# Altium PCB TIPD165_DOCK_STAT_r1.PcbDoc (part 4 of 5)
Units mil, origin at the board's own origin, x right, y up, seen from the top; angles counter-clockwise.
Board outline 6950 x 2800 mil, 2 copper layers (Primary Side, Secondary Side), stack 12.7 mil thick; 32 components, 163 nets, 1211 pads, 80 vias.
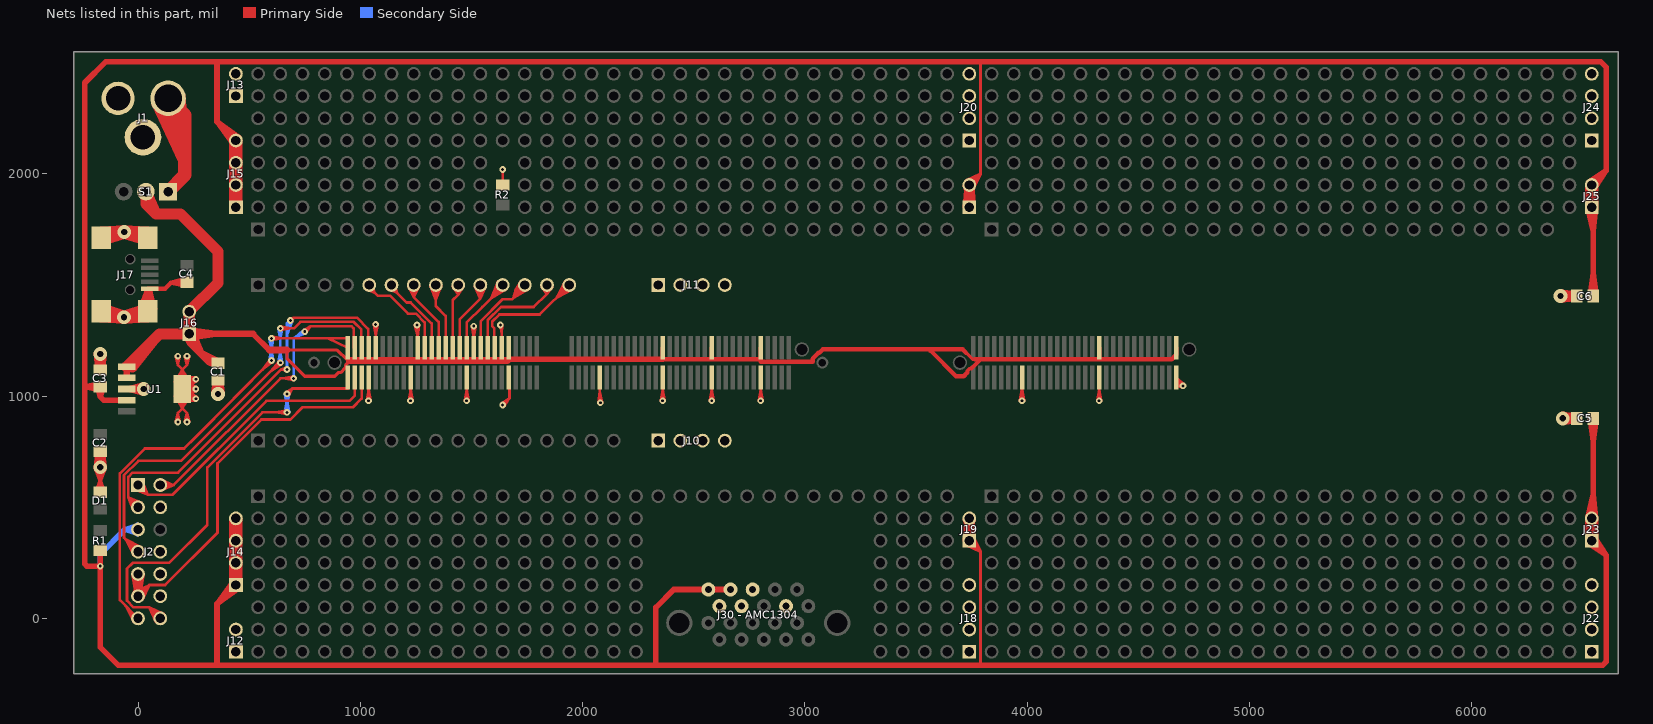
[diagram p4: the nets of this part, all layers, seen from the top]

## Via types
v1: diameter 30/30 (per signal layer), hole 13, Primary Side to Secondary Side, 70 vias
v2: diameter 62/62 (per signal layer), hole 28, Primary Side to Secondary Side, 9 vias
v3: diameter 30, hole 13, Primary Side to Secondary Side, 1 vias

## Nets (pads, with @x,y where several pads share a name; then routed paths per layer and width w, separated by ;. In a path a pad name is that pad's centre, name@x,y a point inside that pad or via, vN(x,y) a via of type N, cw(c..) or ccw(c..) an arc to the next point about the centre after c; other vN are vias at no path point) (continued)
$$$26262: pad.6@1040,1500 pad.24@1289.46,1217.86 | length 611.6
  Primary Side w12: pad.6@1024.56,1480.34 1065,1464.46 ; pad.6@1030.61,1491.01 1065,1464.46 ; pad.6@1051.63,1505.81 1065,1464.46 ; pad.24@1289.46,1217.86 1289.46,1331.14 1249.6,1371 1214.77,1371 1134.77,1451 1078.46,1451 1065,1464.46 ; 1065,1464.46 pad.6@1040,1500 1038.89,1499.17 1065,1464.46
$$$26267: pad.7@1140,1500 pad.26@1320.95,1217.86 | length 540.4
  Primary Side w12: pad.7@1124.56,1480.34 1165,1464.46 ; pad.7@1130.61,1491.01 1165,1464.46 ; pad.7@1151.63,1505.81 1165,1464.46 ; pad.26@1320.95,1217.86 1320.95,1326.52 1226.47,1421 1208.46,1421 1165,1464.46 ; 1165,1464.46 1138.89,1499.17 pad.7@1140,1500 1165,1464.46
$$$26270: pad.8@1240,1500 pad.28@1352.45,1217.86 | length 600.4
  Primary Side w12: pad.8@1215.67,1494.25 1240,1445.67 ; pad.8@1227.09,1498.44 1240,1445.67 ; pad.8@1252.91,1498.44 1240,1445.67 ; pad.8@1264.33,1494.25 1240,1445.67 ; pad.28@1352.45,1217.86 1352.45,1333.22 1240,1445.67 ; 1240,1445.67 pad.8@1240,1500 1240,1445.67
$$$26274: pad.9@1340,1500 pad.30@1383.94,1217.86 | length 635.3
  Primary Side w12: pad.9@1315.44,1495.34 1340,1433 ; pad.9@1327.06,1498.74 1340,1433 ; pad.9@1352.94,1498.74 1340,1433 ; pad.9@1364.56,1495.34 1340,1433 ; pad.30@1383.94,1217.86 1383.94,1360.4 1340,1404.34 pad.9@1340,1500 1340,1433
$$$26277: pad.10@1440,1500 pad.32@1415.44,1217.86 | length 512.3
  Primary Side w12: pad.32@1415.44,1217.86 1415.44,1431.44 1440,1456 ; pad.10@1416.03,1492.9 1440,1456 ; pad.10@1427.14,1498.08 1440,1456 ; pad.10@1452.86,1498.08 1440,1456 ; pad.10@1463.97,1492.9 1440,1456 ; 1440,1456 pad.10@1440,1500 1440,1456
$$$26281: pad.11@1540,1500 pad.34@1446.94,1217.86 | length 629.5
  Primary Side w12: pad.34@1446.94,1217.86 1446.94,1345.17 1540,1438.23 ; pad.11@1515.52,1494.94 1540,1438.23 ; pad.11@1527.07,1498.63 1540,1438.23 ; pad.11@1552.93,1498.63 1540,1438.23 ; pad.11@1564.48,1494.94 1540,1438.23 ; 1540,1438.23 pad.11@1540,1500 1540,1438.23
$$$26286: pad.12@1640,1500 pad.36@1478.43,1217.86 | length 744.8
  Primary Side w12: pad.36@1478.43,1217.86 1478.43,1331.03 1549.4,1402 1549.6,1402 1643.8,1496.2 pad.12@1640,1500 1588.43,1440.83 ; pad.12@1618.78,1513.21 1588.43,1440.83 ; pad.12@1629.53,1507.7 1588.43,1440.83 ; pad.12@1649.06,1490.68 1588.43,1440.83 ; pad.12@1655.99,1480.78 1588.43,1440.83
$$$26290: pad.13@1740,1500 pad.40@1541.43,1217.86 | length 863.2
  Primary Side w12: pad.40@1541.43,1217.86 1541.43,1336.76 1640.66,1436 1683.6,1436 1743.8,1496.2 pad.13@1740,1500 1689.12,1441.52 ; 1697.23,1476.63 1718.74,1513.15 1689.12,1441.52 ; 1698.92,1480.81 1689.12,1441.52 ; pad.13@1729.51,1507.68 1689.12,1441.52 ; pad.13@1749.06,1490.67 1689.12,1441.52 ; pad.13@1755.97,1480.76 1689.12,1441.52
$$$26294: pad.14@1840,1500 pad.42@1572.92,1217.86 | length 679.2
  Primary Side w12: pad.42@1572.92,1217.86 1572.92,1341.39 1632.53,1401 1780,1401 1839,1460 ; pad.14@1816.06,1492.79 1839,1460 ; pad.14@1827.12,1498.21 1839,1460 ; pad.14@1852.77,1497.57 1839,1460 ; pad.14@1863.55,1491.6 1839,1460 ; 1839,1460 1839,1499 pad.14@1840,1500 1839,1460
$$$26299: pad.15@1940,1500 pad.44@1604.42,1217.86 | length 936.2
  Primary Side w12: pad.44@1604.42,1217.86 1603,1219.28 1603,1305 1593,1315 1593,1334.6 1625.4,1367 1807,1367 pad.15@1940,1500 1883.54,1443.54 ; pad.15@1919.77,1514.69 1883.54,1443.54 ; pad.15@1930.09,1508.41 1883.54,1443.54 ; pad.15@1948.41,1490.09 1883.54,1443.54 ; pad.15@1954.69,1479.77 1883.54,1443.54
$$$26449: J1.2 S1.1 | length 1347.6
  Primary Side w60: J1.2@88.03,2322.87 210,2061.42 ; S1.1@135,1920 210,1995 210,2265 J1.2@135,2340 210,2061.42 ; J1.2@184.23,2348.77 210,2061.42
+3V3: "J30 - AMC1304.a8" "J30 - AMC1304.a10" C3.2 C5.2 C6.2 J2.5 J14.1 J14.2 J14.3 J14.4 J15.1 J15.2 J15.3 J15.4 J19.1 J19.2 J23.1 J23.2 J25.1 J25.2 pad.1@3740,1850 pad.2@3740,1950 R1.1 U1.4 | length 36424.3
  Primary Side w15: J19.1@3716.55,348.44 J19.2@3723.13,426.6 ; J19.1@3716.57,351.82 J19.2@3734.14,426.15 ; pad.1@3716.55,1848.44 pad.2@3723.13,1926.6 ; pad.1@3716.57,1851.82 pad.2@3734.14,1926.15 ; J19.1@3716.78,353.63 J19.2@3740,426 ; J19.2@3716.78,446.37 J19.1@3740,374 ; pad.1@3716.78,1853.63 pad.2@3740,1926 ; pad.2@3716.78,1946.37 pad.1@3740,1874 ; J19.1@3717.13,355.39 J19.2@3745.86,426.15 ; pad.1@3717.13,1855.39 pad.2@3745.86,1926.15 ; J19.1@3718.07,358.44 J19.2@3756.87,426.6 ; pad.1@3718.07,1858.44 pad.2@3756.87,1926.6 ; J19.1@3726.38,330.85 3790,300 ; pad.2@3726.38,1969.15 3790,2000 ; J19.1@3731.5,349.82 J19.2@3734.14,426.15 ; J19.1@3731.51,350.48 J19.2@3740,426 ; J19.2@3731.51,449.52 J19.1@3740,374 ; pad.1@3731.5,1849.82 pad.2@3734.14,1926.15 ; pad.1@3731.51,1850.48 pad.2@3740,1926 ; pad.2@3731.51,1949.52 pad.1@3740,1874 ; J19.1@3731.57,351.12 J19.2@3745.86,426.15 ; pad.1@3731.57,1851.12 pad.2@3745.86,1926.15 ; J19.1@3731.61,348.62 J19.2@3723.13,426.6 ; pad.1@3731.61,1848.62 pad.2@3723.13,1926.6 ; J19.1@3731.81,352.28 J19.2@3756.87,426.6 ; pad.1@3731.81,1852.28 pad.2@3756.87,1926.6 ; J19.1@3734.36,343.64 3790,300 ; pad.2@3734.36,1956.36 3790,2000 ; J19.2@3740,450 J19.1@3740,350 ; J19.1@3746.36,355.64 3790,300 ; pad.2@3746.36,1944.36 3790,2000 ; J19.1@3748.19,352.28 J19.2@3723.13,426.6 ; pad.1@3748.19,1852.28 pad.2@3723.13,1926.6 ; J19.1@3748.39,348.62 J19.2@3756.87,426.6 ; pad.1@3748.39,1848.62 pad.2@3756.87,1926.6 ; J19.1@3748.43,351.12 J19.2@3734.14,426.15 ; pad.1@3748.43,1851.12 pad.2@3734.14,1926.15 ; J19.1@3748.5,349.82 J19.2@3745.86,426.15 ; J19.1@3748.49,350.48 J19.2@3740,426 ; J19.2@3748.49,449.52 J19.1@3740,374 ; pad.1@3748.5,1849.82 pad.2@3745.86,1926.15 ; pad.1@3748.49,1850.48 pad.2@3740,1926 ; pad.2@3748.49,1949.52 pad.1@3740,1874 ; J19.1@3759.15,363.62 3790,300 ; pad.2@3759.15,1936.38 3790,2000 ; J19.1@3761.93,358.44 J19.2@3723.13,426.6 ; pad.1@3761.93,1858.44 pad.2@3723.13,1926.6 ; J19.1@3762.87,355.39 J19.2@3734.14,426.15 ; pad.1@3762.87,1855.39 pad.2@3734.14,1926.15 ; J19.1@3763.22,353.63 J19.2@3740,426 ; J19.2@3763.22,446.37 J19.1@3740,374 ; pad.1@3763.22,1853.63 pad.2@3740,1926 ; pad.2@3763.22,1946.37 pad.1@3740,1874 ; J19.1@3763.45,348.44 J19.2@3756.87,426.6 ; J19.1@3763.43,351.82 J19.2@3745.86,426.15 ; pad.1@3763.45,1848.44 pad.2@3756.87,1926.6 ; pad.1@3763.43,1851.82 pad.2@3745.86,1926.15 ; 3790,-210 3790,300 ; 3790,2505 3790,2000 ; J19.2@3723.13,426.6 J19.1@3740,350 ; pad.2@3723.13,1926.6 pad.1@3740,1850 ; J19.2@3734.14,426.15 J19.1@3740,350 ; pad.2@3734.14,1926.15 pad.1@3740,1850 ; J19.1@3740,350 3790,300 ; J19.1@3740,350 J19.2@3745.86,426.15 ; J19.1@3740,350 J19.2@3756.87,426.6 ; pad.1@3740,1850 pad.2@3740,1950 3790,2000 ; pad.1@3740,1850 pad.2@3745.86,1926.15 ; pad.1@3740,1850 pad.2@3756.87,1926.6
  Primary Side w25: C3.2@-182.87,1040.64 -170,997 ; C3.2@-175.28,1029.56 -240,1042.5 ; C3.2@-175.28,1055.44 -240,1042.5 ; C3.2@-174,1042.5 -240,1042.5 ; R1.1@-170,305 v1(-170,235) ; C3.2@-157.13,1040.64 -170,997 ; U1.4@-76,982 -155,982 ; U1.4@-51,982 -155,982 ; J14.1@421.58,148.29 J14.2@421.58,248.29 ; J14.1@421.58,151.71 J14.2@440,250 ; J14.2@421.58,251.71 J14.3@440,350 ; J14.3@421.58,351.71 J14.4@440,450 ; J15.1@421.58,1848.29 J15.2@421.58,1948.29 ; J15.1@421.58,1851.71 J15.2@440,1950 ; J15.2@421.58,1951.71 J15.3@440,2050 ; J15.3@421.58,2051.71 J15.4@440,2150 ; J14.1@422.21,155.08 J14.2@458.42,248.29 ; J14.2@422.21,255.08 J14.3@458.42,348.29 ; J14.3@422.21,355.08 J14.4@458.42,448.29 ; J15.1@422.21,1855.08 J15.2@458.42,1948.29 ; J15.2@422.21,1955.08 J15.3@458.42,2048.29 ; J15.3@422.21,2055.08 J15.4@458.42,2148.29 ; J14.1@425.94,162.02 355.97,65.97 ; J15.4@425.94,2137.98 355.97,2234.03 J15.4@452.02,2164.06 ; J14.1@452.02,135.94 355.97,65.97 ; J14.1@457.79,155.08 J14.2@421.58,248.29 ; J14.2@457.79,255.08 J14.3@421.58,348.29 ; J14.3@457.79,355.08 J14.4@421.58,448.29 ; J15.1@457.79,1855.08 J15.2@421.58,1948.29 ; J15.2@457.79,1955.08 J15.3@421.58,2048.29 ; J15.3@457.79,2055.08 J15.4@421.58,2148.29 ; J14.1@458.42,148.29 J14.2@458.42,248.29 ; J14.1@458.42,151.71 J14.2@440,250 ; J14.2@458.42,251.71 J14.3@440,350 ; J14.3@458.42,351.71 J14.4@440,450 ; J15.1@458.42,1848.29 J15.2@458.42,1948.29 ; J15.1@458.42,1851.71 J15.2@440,1950 ; J15.2@458.42,1951.71 J15.3@440,2050 ; J15.3@458.42,2051.71 J15.4@440,2150 ; 2665.31,130 2565.31,130 2410,130 2330,50 2330,-210 ; J23.1@6521.58,348.29 J23.2@6521.58,448.29 ; J23.1@6521.58,351.71 J23.2@6540,450 ; J25.1@6521.58,1848.29 J25.2@6521.58,1948.29 ; J25.1@6521.58,1851.71 J25.2@6540,1950 ; J23.2@6521.73,452.88 6547.5,557.02 ; J25.1@6521.73,1847.12 6547.5,1743 ; J23.1@6522.21,355.08 J23.2@6558.42,448.29 ; J25.1@6522.21,1855.08 J25.2@6558.42,1948.29 ; J23.1@6528.3,335.67 6605,285 ; J25.2@6528.3,1964.33 6605,2015 ; C5.2@6534.53,895.16 6547.5,795.5 ; C6.2@6534.53,1454.84 6547.5,1554.5 ; C5.2@6547.5,896 6547.5,795.5 ; C5.2@6547.5,900 6547.5,457.5 J23.2@6540,450 ; C6.2@6547.5,1450 6547.5,1842.5 J25.1@6540,1850 ; C6.2@6547.5,1454 6547.5,1554.5 ; J23.1@6554.33,361.7 6605,285 ; J25.2@6554.33,1938.3 6605,2015 ; J23.1@6557.79,355.08 J23.2@6521.58,448.29 ; J25.1@6557.79,1855.08 J25.2@6521.58,1948.29 ; J23.1@6558.42,348.29 J23.2@6558.42,448.29 ; J23.1@6558.42,351.71 J23.2@6540,450 ; J25.1@6558.42,1848.29 J25.2@6558.42,1948.29 ; J25.1@6558.42,1851.71 J25.2@6540,1950 ; J23.2@6558.5,450.3 6547.5,557.02 ; J25.1@6558.5,1849.7 6547.5,1743 ; C5.2@6560.47,895.16 6547.5,795.5 ; C6.2@6560.47,1454.84 6547.5,1554.5 ; -240,1042.5 C3.2@-170,1042.5 -170,997 ; -240,1042.5 -240,245 -230,235 v1(-170,235) ; -240,1042.5 -240,2410 -145,2505 355,2505 ; v1(-170,235) -170,-130 -90,-210 355,-210 ; -170,997 -155,982 ; 355,-210 355,65 J14.1@440,150 ; 355,-210 2330,-210 ; 355,2505 355,2235 J15.4@440,2150 ; 355,2505 3790,2505 6580,2505 6605,2480 6605,2015 ; 355.97,65.97 J14.1@440,150 ; J14.2@421.58,248.29 J14.1@440,150 ; J14.2@421.58,248.29 J14.3@421.58,348.29 ; J14.3@421.58,348.29 J14.2@440,250 ; J14.3@421.58,348.29 J14.4@421.58,448.29 ; J14.4@421.58,448.29 J14.3@440,350 ; J15.2@421.58,1948.29 J15.1@440,1850 ; J15.2@421.58,1948.29 J15.3@421.58,2048.29 ; J15.3@421.58,2048.29 J15.2@440,1950 ; J15.3@421.58,2048.29 J15.4@421.58,2148.29 ; J15.4@421.58,2148.29 J15.3@440,2050 ; J14.1@440,150 J14.2@440,250 ; J14.1@440,150 J14.2@458.42,248.29 ; J14.2@440,250 J14.3@440,350 ; J14.2@440,250 J14.3@458.42,348.29 ; J14.3@440,350 J14.4@440,450 ; J14.3@440,350 J14.4@458.42,448.29 ; J15.1@440,1850 J15.2@440,1950 ; J15.1@440,1850 J15.2@458.42,1948.29 ; J15.2@440,1950 J15.3@440,2050 ; J15.2@440,1950 J15.3@458.42,2048.29 ; J15.3@440,2050 J15.4@440,2150 ; J15.3@440,2050 J15.4@458.42,2148.29 ; J14.2@458.42,248.29 J14.3@458.42,348.29 ; J14.3@458.42,348.29 J14.4@458.42,448.29 ; J15.2@458.42,1948.29 J15.3@458.42,2048.29 ; J15.3@458.42,2048.29 J15.4@458.42,2148.29 ; 2330,-210 3790,-210 6590,-210 6605,-195 6605,285 ; J23.2@6521.58,448.29 J23.1@6540,350 ; J25.2@6521.58,1948.29 J25.1@6540,1850 ; J23.1@6540,350 6605,285 ; J23.1@6540,350 J23.2@6540,450 ; J23.1@6540,350 J23.2@6558.42,448.29 ; J23.2@6540,450 6547.5,557.02 ; J25.1@6540,1850 J25.2@6540,1950 ; J25.1@6540,1850 J25.2@6558.42,1948.29 ; J25.1@6540,1850 6547.5,1743 ; J25.2@6540,1950 6605,2015
  Secondary Side w25: v1(-170,235) -170,290 -60,400 ; J2.5@-2.85,381.72 -60,400 ; J2.5@-2.85,418.28 -60,400 ; J2.5@0,400 -60,400
+5V: C1.2 J16.1 J16.2 pad.48@1667.41,1217.86 pad.84@2360.32,1217.86 pad.98@2580.8,1217.86 pad.112@2801.27,1217.86 pad.158@4323.63,1217.86 pad.180@4670.09,1217.86 S1.2 U1.1 U1.2 | length 8765.2
  Primary Side w12: C1.2@357.5,1150 C1.2@360,1147.5 ; pad.48@1667.41,1165 pad.48@1667.41,1217.86
  Primary Side w15: 944.58,1154.61 946.45,1156.48 ; 949.97,1160 946.45,1156.48 ; 3725,1195 3755,1165 3765,1165 ; 946.45,1156.48 940,1162.92 895,1207.5 670,1207.5 670,1170 750,1090 885,1090 900.99,1105.99 910.99,1105.99 932.97,1127.97 932.97,1137.97 948.96,1153.96 946.45,1156.48
  Primary Side w17: 3729.86,1104.86 3731.36,1106.36 3731.36,1114.04 3740.44,1123.12 3748.12,1123.12 3749.62,1124.62
  Primary Side w20: pad.84@2360.32,1217.86 2360,1165 2579,1165 pad.98@2580,1166 ; pad.98@2580.8,1217.86 2580,1217.86 pad.98@2580,1166 ; pad.112@2801.27,1217.86 2801,1217.86 pad.112@2801,1166 ; 3725,1195 3710,1210 3565,1210 ; 3729.86,1104.86 3715,1090 3680,1090 3565,1205 3565,1210 ; 3749.62,1124.62 3790,1165 ; 3765,1165 3790,1165 ; pad.158@4323.63,1217.86 4324,1217.86 4324,1166 4650,1166 4670,1186 4670,1217.77 pad.180@4670.09,1217.86 ; 4347,1165 3790,1165 ; pad.98@2580,1166 pad.112@2801,1166 ; pad.112@2801,1166 2801,1155 3035.29,1155 3035.29,1168.96 3060.8,1194.47 3064.47,1194.47 3080,1210 3565,1210
  Primary Side w25: J16.1@215.01,1269.16 293.37,1176.63 ; J16.1@246.46,1288.44 293.37,1176.63 ; C1.2@348.28,1137.04 259.11,1210.89 ; C1.2@357.5,1150 320,1150 ; C1.2@362.5,1158.76 259.11,1210.89 ; 517.5,1280 590,1207.5 ; pad.48@1667.41,1165 pad.84@2360,1165 ; 230,1240 J16.1@230,1280 ; 230,1240 320,1150 ; 230,1240 248,1275.72 230,1240 ; 230,1240 212,1275.72 230,1240 ; 230,1240 J16.1@230,1280 ; J16.1@230,1280 293.37,1176.63 ; 259.11,1210.89 C1.2@356,1147.5 ; 320,1150 352.78,1134.91 320,1150 ; 320,1150 354.55,1160.42 320,1150 ; 320,1150 C1.2@356,1147.5 ; 320,1150 C1.2@356,1147.5
  Primary Side w30: U1.2@-51,1082 U1.1@-51,1132 ; J16.1@230,1280 517.5,1280 ; J16.1@231.06,1264.03 351,1280 J16.1@231.06,1295.97 ; 590,1207.5 670,1207.5 ; 949.97,1160 1662.41,1160 pad.48@1667.41,1165
  Primary Side w50: U1.1@-51,1132 97,1280 J16.1@230,1280 J16.2@230,1380 360,1510 360,1650 190,1820 80,1820 ; U1.1@-26,1132 70.07,1253.07 ; 35,1865 S1.2@35,1920 ; 35,1865 80,1820 ; 35,1865 S1.2@35,1920 ; S1.2@35,1920 80,1820
\TRST\: J2.2 pad.4@974.5,1217.86 | length 1992.5
  Primary Side w12: J2.2@100,600 160,600 ; J2.2@101.41,587.08 160,600 ; J2.2@101.41,612.92 160,600 ; J2.2@105.21,575.55 160,600 ; J2.2@105.21,624.45 160,600 ; v1@699.21,1071.04 649,1080 ; v1@699.21,1088.96 649,1080 ; v1@744.5,1297.12 775,1315 ; v1(750,1290) 775,1315 ; v1@757.12,1284.5 775,1315 ; pad.4@974.5,1217.86 970,1217.86 970,1305 960,1315 775,1315 ; 160,600 640,1080 v1(700,1080) 649,1080
  Secondary Side w12: v1(700,1080) 700,1260 740,1290 v1(750,1290) 702.96,1262.22 ; v1@744.8,1297.35 702.96,1262.22 ; v1@753.92,1281.9 702.96,1262.22
EMU0: J2.13 pad.2@943,1217.86 | length 2801.4
  Primary Side w12: J2.13@-20.23,-14.69 -56.46,56.46 J2.13@-9.91,-8.41 ; J2.13@0,0 -82,82 -82,652.12 30.44,764.56 207.56,764.56 258,815 v1(600,1160) 559.79,1119.43 ; v1@593.13,1165.81 559.79,1119.43 ; v1(600,1260) 943,1260 pad.2@943,1217.86 852.46,1260 ; v1@600.79,1251.04 651,1260 v1@600.79,1268.96 ; v1@605.87,1153.18 559.79,1119.43
  Secondary Side w12: v1@591.04,1160.79 600,1211 v1@608.96,1160.79 ; v1@591.04,1259.21 600,1209 v1@608.96,1259.21 ; v1(600,1160) v1(600,1260)
EMU1: J2.14 pad.1@943,1084 | length 2612.7
  Primary Side w12: J2.14@79.48,-14.27 50,50 ; J2.14@90,-8.31 50,50 ; J2.14@100,0 50,50 ; J2.14@108.31,10 50,50 ; J2.14@114.27,20.52 50,50 ; v1@664.54,1017.15 694,1034 ; v1@669.21,918.04 619,927 ; v1@669.21,935.96 619,927 ; v1(670,1010) 694,1034 ; v1@677.15,1004.54 694,1034 ; pad.1@943,1084 943,1034 694,1034 ; 50,50 -20,50 -50,80 -50,224 -24,250 140,250 311.37,421.37 311.37,678.63 559.75,927 v1(670,927) 619,927
  Secondary Side w12: v1@661.04,927.79 670,978 v1@678.96,927.79 ; v1@661.04,1009.21 670,959 v1@678.96,1009.21 ; v1(670,927) v1(670,1010)
GND: "J30 - AMC1304.a3" "J30 - AMC1304.a6" "J30 - AMC1304.a7" "J30 - AMC1304.a9" C1.1 C2.1 C3.1 C4.1 C5.1 C6.1 D1.1 J1.1 J1.3 J2.4 J2.8 J2.10 J2.12 J10.1 J10.2 J10.3 J10.4 J11.1 J11.2 J11.3 J11.4 J12.1 J12.2 J13.1 J13.2 J17.5 J17.6 J17.7 J17.8 J17.9 J18.1 J18.2 J18.3 J18.4 J20.1 J20.2 J20.3 J20.4 J22.1 J22.2 J22.3 J22.4 J24.1 J24.2 J24.3 J24.4 pad.7@1037.49,1084 pad.10@1068.98,1217.86 pad.19@1226.46,1084 pad.22@1257.96,1217.86 pad.35@1478.43,1084 pad.38@1509.93,1217.86 pad.46@1635.91,1217.86 pad.47@1667.41,1084 pad.65@2076.86,1084 pad.83@2360.32,1084 pad.97@2580.8,1084 pad.111@2801.27,1084 pad.135@3977.17,1084 pad.157@4323.63,1084 pad.179@4670.09,1084 R2.2 U1.3 U1.6 | length 26797.5
  Primary Side w12: v2@-194.91,677.9 C2.1@-188.09,745.87 ; v2@-194.91,682.12 C2.1@-176.85,746.84 ; v2@-194.91,1187.88 C3.1@-176.85,1123.16 ; v2@-194.91,1192.1 C3.1@-188.09,1124.13 ; v2@-194.56,675.34 -170,613 ; v2@-194.56,684.66 C2.1@-170,747 ; v2@-194.56,1185.34 C3.1@-170,1123 ; v2@-193.96,687.13 C2.1@-163.15,746.84 ; v2@-193.96,1182.87 C3.1@-163.15,1123.16 ; v2@-192.49,690.92 C2.1@-151.91,745.87 ; v2@-192.49,1179.08 C3.1@-151.91,1124.13 ; D1.1@-189.25,570.59 -170,629 ; C2.1@-189.25,749.41 v2@-170,691 ; C3.1@-189.25,1120.59 v2@-170,1179 ; v2@-183,679.93 C2.1@-176.85,746.84 ; v2@-183,1190.07 C3.1@-176.85,1123.16 ; v2@-182.94,678.74 -170,613 ; v2@-182.94,681.26 C2.1@-170,747 ; v2@-182.94,1188.74 C3.1@-170,1123 ; v2@-182.81,677.77 C2.1@-188.09,745.87 ; v2@-182.81,1192.23 C3.1@-188.09,1124.13 ; v2@-182.74,682.57 C2.1@-163.15,746.84 ; v2@-182.74,1187.43 C3.1@-163.15,1123.16 ; v2@-182.15,684.62 C2.1@-151.91,745.87 ; v2@-182.15,1185.38 C3.1@-151.91,1124.13 ; D1.1@-177.49,567.96 -170,629 ; C2.1@-177.49,752.04 v2@-170,691 ; C3.1@-177.49,1117.96 v2@-170,1179 ; D1.1@-170,567.5 v2(-170,680) ; C2.1@-170,752.5 v2(-170,680) ; C3.1@-170,1117.5 v2(-170,1190) ; D1.1@-162.51,567.96 -170,629 ; C2.1@-162.51,752.04 v2@-170,691 ; C3.1@-162.51,1117.96 v2@-170,1179 ; v2@-157.85,684.62 C2.1@-188.09,745.87 ; v2@-157.85,1185.38 C3.1@-188.09,1124.13 ; v2@-157.26,682.57 C2.1@-176.85,746.84 ; v2@-157.26,1187.43 C3.1@-176.85,1123.16 ; v2@-157.19,677.77 C2.1@-151.91,745.87 ; v2@-157.19,1192.23 C3.1@-151.91,1124.13 ; v2@-157.06,678.74 -170,613 ; v2@-157.06,681.26 C2.1@-170,747 ; v2@-157.06,1188.74 C3.1@-170,1123 ; v2@-157,679.93 C2.1@-163.15,746.84 ; v2@-157,1190.07 C3.1@-163.15,1123.16 ; D1.1@-150.75,570.59 -170,629 ; C2.1@-150.75,749.41 v2@-170,691 ; C3.1@-150.75,1120.59 v2@-170,1179 ; v2@-147.51,690.92 C2.1@-188.09,745.87 ; v2@-147.51,1179.08 C3.1@-188.09,1124.13 ; v2@-146.04,687.13 C2.1@-176.85,746.84 ; v2@-146.04,1182.87 C3.1@-176.85,1123.16 ; v2@-145.44,675.34 -170,613 ; v2@-145.44,684.66 C2.1@-170,747 ; v2@-145.44,1185.34 C3.1@-170,1123 ; v2@-145.09,677.9 C2.1@-151.91,745.87 ; v2@-145.09,682.12 C2.1@-163.15,746.84 ; v2@-145.09,1187.88 C3.1@-163.15,1123.16 ; v2@-145.09,1192.1 C3.1@-151.91,1124.13 ; U1.6@166.22,999.97 199,945 ; U1.6@166.22,1064.03 199,1119 ; v1@170.06,885.01 179,924 ; v1@170.06,1178.99 179,1140 ; U1.6@177.33,1005.22 199,945 ; U1.6@177.33,1058.78 199,1119 ; v1(179,884) 179,924 ; v1@187.94,885.01 179,924 ; v1@187.94,1178.99 179,1140 ; U1.6@189.03,1008.22 199,945 ; U1.6@189.03,1055.78 199,1119 ; U1.6@195.49,987.28 v1(260,988) ; U1.6@195.49,1076.72 v1(260,1076) ; U1.6@196.49,999.32 v1(260,988) ; U1.6@196.49,1064.68 v1(260,1076) ; U1.6@196.8,975.07 v1(260,988) ; U1.6@196.8,1088.93 v1(260,1076) ; U1.6@199.82,1022.03 v1(260,1032) ; U1.6@199.82,1041.97 v1(260,1032) ; U1.6@202.97,1010.36 v1(260,1032) ; U1.6@202.97,1053.64 v1(260,1032) ; U1.6@202.98,1018.17 v1(260,988) ; U1.6@202.98,1045.83 v1(260,1076) ; U1.6@208.48,999.35 v1(260,1032) ; U1.6@208.48,1064.65 v1(260,1032) ; U1.6@208.97,1008.22 199,945 ; U1.6@208.97,1055.78 199,1119 ; U1.6@209.6,1028.28 v1(260,988) ; U1.6@209.6,1035.72 v1(260,1076) ; v1@211.06,885.01 220,924 ; v1@211.06,1178.99 220,1140 ; U1.6@218.15,1026.9 v1(260,1076) ; U1.6@218.15,1037.1 v1(260,988) ; v1(220,884) 220,924 ; U1.6@220.67,1005.22 199,945 ; U1.6@220.67,1058.78 199,1119 ; v1@228.94,885.01 220,924 ; v1@228.94,1178.99 220,1140 ; U1.6@231.78,999.97 199,945 ; U1.6@231.78,1064.03 199,1119 ; v1@252.7,982.73 U1.6@223.86,1030.4 ; v1@252.7,1081.27 U1.6@223.86,1033.6 ; v1@253.83,981.45 U1.6@216.88,1022.46 ; v1@253.83,1082.55 U1.6@216.88,1041.54 ; v1@254.56,1024.83 U1.6@214.59,1060.78 ; v1@254.56,1039.17 U1.6@214.59,1003.22 ; v1@255.13,980.43 U1.6@213.18,1012.78 ; v1@255.13,1083.57 U1.6@213.18,1051.22 ; v1@256.09,1023.89 U1.6@211.34,1050.46 ; v1@256.09,1040.11 U1.6@211.34,1013.54 ; v1@256.34,979.78 U1.6@210.96,1004.88 ; v1@256.34,1084.22 U1.6@210.96,1059.12 ; v1@257.43,996.63 U1.6@209.73,977.72 ; v1@257.43,1067.37 U1.6@209.73,1086.28 ; v1@257.65,979.31 U1.6@209.56,996.99 ; v1@257.65,1084.69 U1.6@209.56,1067.01 ; v1@257.76,1023.28 U1.6@209.48,1040.37 ; v1@257.76,1040.72 U1.6@209.48,1023.63 ; v1@259.11,996.96 U1.6@209,987.43 ; v1@259.11,1067.04 U1.6@209,1076.57 ; v1@259.21,979.04 U1.6@209,988 ; v1@259.21,996.96 U1.6@209,988 ; v1@259.21,1023.04 U1.6@209,1032 ; v1@259.21,1040.96 U1.6@209,1032 ; v1@259.21,1067.04 U1.6@209,1076 ; v1@259.21,1084.96 U1.6@209,1076 ; v1@259.31,979.03 U1.6@209,987.43 ; v1@259.31,1084.97 U1.6@209,1076.57 ; v1@260.68,1023.03 U1.6@209.48,1023.63 ; v1@260.68,1040.97 U1.6@209.48,1040.37 ; v1@260.79,996.96 U1.6@209.56,996.99 ; v1@260.79,1067.04 U1.6@209.56,1067.01 ; v1@261.02,979.06 U1.6@209.73,977.72 ; v1@261.02,1084.94 U1.6@209.73,1086.28 ; v1@262.18,996.73 U1.6@210.96,1004.88 ; v1@262.18,1067.27 U1.6@210.96,1059.12 ; v1@262.45,1023.34 U1.6@211.34,1013.54 ; v1@262.45,1040.66 U1.6@211.34,1050.46 ; v1@263.52,996.28 U1.6@213.18,1012.78 ; v1@263.52,1067.72 U1.6@213.18,1051.22 ; v1@264.16,1024.02 U1.6@214.59,1003.22 ; v1@264.16,1039.98 U1.6@214.59,1060.78 ; v1@265.03,995.47 U1.6@216.88,1022.46 ; v1@265.03,1068.53 U1.6@216.88,1041.54 ; v1@266.36,994.37 U1.6@223.86,1030.4 ; v1@266.36,1069.63 U1.6@223.86,1033.6 ; v1@1028.04,979.79 1037,1030 v1@1045.96,979.79 ; v1(1037,979) 1037,1038 1037.49,1038 pad.7@1037.49,1084 ; v1@1060.04,1322.21 1069,1272 v1@1077.96,1322.21 ; pad.10@1068.98,1217.86 1068.98,1262 v1(1069,1323) ; v1@1217.04,979.79 1226,1030 v1@1234.96,979.79 ; v1(1226,979) 1226,1038 1226.46,1038 pad.19@1226.46,1084 ; v1@1246.1,1318.69 pad.22@1257.96,1268.79 ; pad.22@1257.96,1217.86 1257.96,1320 v1(1255,1320) pad.22@1257.96,1268.79 ; v1@1264,1319.73 pad.22@1257.96,1268.79 ; v1@1469.04,979.87 1478.43,1030 ; pad.35@1478.43,1084 1478.43,979 v1(1478,979) 1478.43,1030 ; v1@1486.97,979.72 1478.43,1030 ; v1@1501.03,1314.22 pad.38@1509.93,1264 ; pad.38@1509.93,1217.86 1509.93,1263 v1(1510,1315) pad.38@1509.93,1264 ; v1@1518.96,1314.19 pad.38@1509.93,1264 ; v1(1630,1320) 1635.91,1280 ; v1@1634.32,966.98 1670.93,990.93 ; pad.46@1635.91,1217.86 1635.91,1280 ; v1@1638.99,1320.32 1635.91,1280 ; v1(1640,960) 1670.93,990.93 ; R2.2@1640,1950 v3(1640,2020) ; v1@1646.98,954.32 1670.93,990.93 ; pad.47@1667.41,1084 1670.93,1084 1670.93,990.93 ; v1@2071,970.24 2076.86,1021.31 ; pad.65@2076.86,1084 2076.86,973.14 v1(2080,970) 2076.86,1021.31 ; v1@2088.9,971.33 2076.86,1021.31 ; v1@2351.04,979.85 2360.32,1030 ; pad.83@2360.32,1084 2360.32,979 v1(2360,979) 2360.32,1030 ; v1@2368.97,979.74 2360.32,1030 ; v1@2572.03,979.76 2580.81,1030 ; pad.97@2580.8,1084 2580.8,1035 v1(2581,979) 2580.81,1030 ; v1@2589.96,979.83 2580.81,1030 ; v1@2792.04,979.79 2801,1030 v1@2809.96,979.79 ; v1(2801,979) 2801,1035 2801.27,1035 pad.111@2801.27,1084 ; v1@3968.04,979.79 3977,1030 v1@3985.96,979.79 ; v1(3977,979) 3977,1039 3977.17,1039 pad.135@3977.17,1084 ; v1@4315.04,979.79 4324,1030 v1@4332.96,979.79 ; pad.157@4323.63,1084 4323.63,1039 4324,1039 v1(4324,979) ; v1@4693.53,1040.99 pad.179@4670.09,1084 ; v1@4699.69,1037.1 pad.179@4670.09,1046 ; v1@4699.69,1054.9 pad.179@4670.09,1046 ; v1@4707.43,1052.3 pad.179@4670.09,1084 ; v2@6397.77,1437.19 C6.1@6465.87,1431.91 ; v2@6397.77,1462.81 C6.1@6465.87,1468.09 ; v2@6397.9,1425.09 C6.1@6465.87,1431.91 ; v2@6397.9,1474.91 C6.1@6465.87,1468.09 ; v2@6399.93,1437 C6.1@6466.84,1443.15 ; v2@6399.93,1463 C6.1@6466.84,1456.85 ; v2@6401.26,1437.06 C6.1@6467,1450 ; v2@6401.26,1462.94 C6.1@6467,1450 ; v2@6402.12,1425.09 C6.1@6466.84,1443.15 ; v2@6402.12,1474.91 C6.1@6466.84,1456.85 ; v2@6402.57,1437.26 C6.1@6466.84,1456.85 ; v2@6402.57,1462.74 C6.1@6466.84,1443.15 ; v2@6404.62,1437.85 C6.1@6465.87,1468.09 ; v2@6404.62,1462.15 C6.1@6465.87,1431.91 ; v2@6404.66,1425.44 C6.1@6467,1450 ; v2@6404.66,1474.56 C6.1@6467,1450 ; v2@6407.13,1426.04 C6.1@6466.84,1456.85 ; v2@6407.13,1473.96 C6.1@6466.84,1443.15 ; v2@6407.21,875.16 C5.1@6469.41,880.75 ; v2@6407.21,924.84 C5.1@6469.41,919.25 ; v2@6407.3,887.28 C5.1@6469.41,880.75 ; v2@6407.3,912.72 C5.1@6469.41,919.25 ; v2@6409.79,887 C5.1@6472.04,892.51 ; v2@6409.79,913 C5.1@6472.04,907.49 ; v2@6410.92,1427.51 C6.1@6465.87,1468.09 ; v2@6410.92,1472.49 C6.1@6465.87,1431.91 ; v2@6412.03,875.08 C5.1@6472.04,892.51 ; v2@6412.03,924.92 C5.1@6472.04,907.49 ; v2@6412.89,887.33 C5.1@6472.04,907.49 ; v2@6412.89,912.67 C5.1@6472.04,892.51 ; v2@6415.27,888.12 C5.1@6469.41,919.25 ; v2@6415.27,911.88 C5.1@6469.41,880.75 ; v2@6417.9,876.28 C5.1@6472.04,907.49 ; v2@6417.9,923.72 C5.1@6472.04,892.51 ; v2@6422.31,878.24 C5.1@6469.41,919.25 ; v2@6422.31,921.76 C5.1@6469.41,880.75 ; C6.1@6469.41,1430.75 v2@6411,1450 ; C6.1@6469.41,1469.25 v2@6411,1450 ; C6.1@6472.04,1442.51 v2@6411,1450 ; C6.1@6472.04,1457.49 v2@6411,1450 ; C6.1@6472.5,1450 v2(6400,1450) ; C2.1@-188.09,745.87 v2(-170,680) ; C3.1@-188.09,1124.13 v2(-170,1190) ; C2.1@-176.85,746.84 v2(-170,680) ; C3.1@-176.85,1123.16 v2(-170,1190) ; v2(-170,680) C2.1@-163.15,746.84 ; v2(-170,680) C2.1@-151.91,745.87 ; v2(-170,1190) C3.1@-163.15,1123.16 ; v2(-170,1190) C3.1@-151.91,1124.13 ; 179,924 199,944 199,945 ; 179,1140 199,1120 199,1119 ; 179,1140 v1(179,1180) 179,1140 ; 199,945 220,924 ; 199,945 199,1009 v1(260,988) ; 199,945 U1.6@199,988 ; U1.6@199,988 v1(260,988) ; U1.6@199,988 U1.6@199,1032 ; U1.6@199,1032 U1.6@199,1076 ; U1.6@199,1032 v1(260,1032) ; U1.6@199,1076 v1(260,1076) ; U1.6@199,1076 199,1119 ; 199,1119 220,1140 ; 199,1119 199,1055 v1(260,1076) ; U1.6@209,987.43 v1(260,988) ; U1.6@209,988 v1(260,988) ; U1.6@209,1032 v1(260,1032) ; U1.6@209,1076 v1(260,1076) ; U1.6@209,1076.57 v1(260,1076) ; U1.6@209.48,1023.63 v1(260,1032) ; U1.6@209.48,1040.37 v1(260,1032) ; U1.6@209.56,996.99 v1(260,988) ; U1.6@209.56,1067.01 v1(260,1076) ; U1.6@209.73,977.72 v1(260,988) ; U1.6@209.73,1086.28 v1(260,1076) ; U1.6@210.96,1004.88 v1(260,988) ; U1.6@210.96,1059.12 v1(260,1076) ; U1.6@211.34,1013.54 v1(260,1032) ; U1.6@211.34,1050.46 v1(260,1032) ; U1.6@213.18,1012.78 v1(260,988) ; U1.6@213.18,1051.22 v1(260,1076) ; U1.6@214.59,1003.22 v1(260,1032) ; U1.6@214.59,1060.78 v1(260,1032) ; U1.6@216.88,1022.46 v1(260,988) ; U1.6@216.88,1041.54 v1(260,1076) ; 220,1140 v1(220,1180) 220,1140 ; U1.6@223.86,1030.4 v1(260,988) ; U1.6@223.86,1033.6 v1(260,1076) ; pad.179@4670.09,1046 v1(4701,1046) pad.179@4670.09,1084 ; pad.179@4670.09,1046 pad.179@4670.09,1084 ; v2(6400,1450) C6.1@6465.87,1431.91 ; v2(6400,1450) C6.1@6465.87,1468.09 ; v2(6400,1450) C6.1@6466.84,1443.15 ; v2(6400,1450) C6.1@6466.84,1456.85 ; v2(6410,900) C5.1@6472.5,900 ; v2(6410,900) C5.1@6469.41,880.75 ; v2(6410,900) C5.1@6469.41,919.25 ; v2(6410,900) C5.1@6472.04,892.51 ; v2(6410,900) C5.1@6472.04,907.49 ; v2(6410,900) C5.1@6472.5,900 ; v2@6411,900 C5.1@6469.41,880.75 ; v2@6411,900 C5.1@6469.41,919.25 ; v2@6411,900 C5.1@6472.04,892.51 ; v2@6411,900 C5.1@6472.04,907.49 ; v2@6411,900 C5.1@6472.5,900 ; C5.1@6472.5,900 6415,924.49 C5.1@6472.5,900 ; C5.1@6472.5,900 6415,875.51 C5.1@6472.5,900 ; C5.1@6472.5,900 6411.35,912.93 C5.1@6472.5,900 ; C5.1@6472.5,900 6411.35,887.07 C5.1@6472.5,900
  Primary Side w20: J17.7@9.69,1393.64 J17.5@43.16,1484.01 ; J17.7@18.43,1417.24 J17.5@53,1484.01 ; J17.7@29.19,1388.66 J17.5@43.16,1484.01 ; J17.7@32.67,1412.36 J17.5@53,1484.01 ; J17.7@43.16,1381.65 J17.5@43.16,1484.01 ; J17.7@43.16,1387.65 J17.5@43.16,1484.01 ; J17.7@53.93,1410.45 J17.5@53,1484.01 ; J17.7@57.12,1388.66 J17.5@43.16,1484.01 ; J17.7@69.54,1412.76 J17.5@53,1484.01 ; J17.7@76.62,1393.64 J17.5@43.16,1484.01 ; J17.5@83,1484.01 122.01,1484.01 ; C4.1@213.67,1527.82 148,1510 ; C4.1@214.8,1497.05 148,1510 ; C4.1@216,1512.5 148,1510 ; C4.1@220,1512.5 217.5,1510 148,1510 ; J17.5@43.16,1484.01 J17.5@53,1484.01 ; J17.5@53,1484.01 122.01,1484.01 ; J17.5@53,1484.01 43.16,1410.63 J17.5@53,1484.01 ; 122.01,1484.01 148,1510
  Primary Side w25: J17.9@-165.5,1381.65 J17.9@-165.5,1355 ; J17.8@-165.5,1712.35 J17.8@-165.5,1738 ; v2@-73.29,1339.62 J17.9@-154.7,1405.24 ; v2@-72.07,1753.52 J17.8@-155.07,1688.63 ; v2@-70.18,1372.05 J17.7@32.71,1405.36 ; v2@-69.1,1720.92 J17.6@32.88,1688.58 ; v2@-68.24,1337.26 J17.9@-165.5,1375.65 ; v2@-67.03,1755.8 J17.8@-165.5,1718.35 ; v2@-66.53,1373.16 J17.9@-167,1344.18 ; v2@-65.68,1719.87 J17.8@-166.69,1749.83 ; v2@-64.94,1373.4 41.62,1375.35 v2@-57.91,1337.22 ; v2@-64.67,1336.58 J17.9@-165.5,1355 ; v2@-64.67,1373.42 J17.9@-165.5,1355 ; v2@-63.81,1719.59 42.72,1718.44 v2@-57.04,1755.82 ; v2@-63.65,1719.57 J17.8@-165.5,1738 ; v2@-63.65,1756.43 J17.8@-165.5,1738 ; v2@-63.24,1336.5 42.62,1344.38 v2@-59.55,1373.18 ; v2@-62.72,1336.5 J17.9@-167,1344.18 ; v2@-62.44,1756.49 43.54,1749.75 v2@-58.36,1719.86 ; v2@-61.54,1756.49 J17.8@-166.69,1749.83 ; v2@-61.39,1336.57 43,1355 v2@-61.39,1373.43 ; v2@-60.97,1373.39 J17.9@-165.5,1375.65 ; v2@-60.37,1719.57 J17.6@43.16,1738 ; v2@-60.37,1756.43 J17.6@43.16,1738 ; v2@-60.16,1719.59 J17.8@-165.5,1718.35 ; v2@-55.58,1371.95 J17.9@-154.7,1405.24 ; v2@-54.8,1720.96 J17.8@-155.07,1688.63 ; v2@-53.02,1339.43 J17.7@32.71,1405.36 ; v2@-52.07,1753.61 J17.6@32.88,1688.58 ; v2@22.71,1013.79 U1.3@-26,1032 ; v2@22.71,1050.21 U1.3@-26,1032 ; v2@23.78,1013.63 U1.3@-51,1032 ; v2@23.78,1050.37 U1.3@-51,1032 ; J17.7@43.16,1375.65 v2(-63,1355) ; J17.7@43.16,1381.65 43.16,1355 v2(-63,1355) ; J17.6@43.16,1712.35 J17.6@43.16,1738 ; J17.6@43.16,1718.35 v2(-62,1738) ; J17.6@44.32,1749.83 v2(-62,1738) ; J17.7@44.6,1344.18 v2(-63,1355) ; v2@341.53,1008.89 C1.1@347.07,1071.15 ; v2@342.67,1016.46 C1.1@372.93,1071.15 ; v2@377.33,1016.46 C1.1@347.07,1071.15 ; v2@378.47,1008.89 C1.1@372.93,1071.15 ; J17.9@-167,1344.18 v2(-63,1355) ; J17.8@-166.69,1749.83 v2(-62,1738) ; J17.9@-165.5,1355 v2(-63,1355) ; J17.9@-165.5,1375.65 v2(-63,1355) ; J17.8@-165.5,1718.35 v2(-62,1738) ; J17.8@-165.5,1738 v2(-62,1738) ; J17.8@-155.07,1688.63 v2(-62,1738) ; J17.9@-154.7,1405.24 v2(-63,1355) ; v2(-63,1355) J17.7@32.71,1405.36 ; v2(-62,1738) J17.6@43.16,1738 ; v2(-62,1738) J17.6@32.88,1688.58 ; U1.3@-51,1032 v2(26,1032) U1.3@-26,1032 ; C1.1@347.07,1071.15 v2(360,1010) ; C1.1@347.07,1071.15 v2(360,1010) ; v2(360,1010) C1.1@360,1072.5 ; v2(360,1010) C1.1@372.93,1071.15 ; v2(360,1010) C1.1@360,1072.5 ; C1.1@360,1072.5 341.7,1012.74 C1.1@360,1072.5 ; C1.1@360,1072.5 378.3,1012.74 C1.1@360,1072.5
TCK: J2.9 J2.11 pad.5@1005.99,1084 | length 4617.8
  Primary Side w12: J2.9@-24.99,200.62 -14.21,130.94 ; J2.9@-24.91,197.9 -6.84,132.24 ; J2.11@-24.56,104.66 0,167 ; J2.9@-24.56,195.34 0,133 ; J2.9@-23.99,192.97 6.84,132.24 ; J2.9@-23.21,190.7 14.21,130.94 ; J2.11@-14.27,120.52 50,150 ; J2.9@-13,200.07 -6.84,132.24 ; J2.11@-12.94,101.26 0,167 ; J2.9@-12.94,198.74 0,133 ; J2.9@-12.92,201.43 -14.21,130.94 ; J2.9@-12.44,196.22 14.21,130.94 ; J2.11@-8.31,110 50,150 ; J2.11@10,91.69 50,150 ; J2.9@12.44,196.22 -14.21,130.94 ; J2.9@12.92,201.43 14.21,130.94 ; J2.11@12.94,101.26 0,167 ; J2.9@12.94,198.74 0,133 ; J2.9@13,200.07 6.84,132.24 ; J2.11@20.52,85.73 50,150 ; J2.9@23.21,190.7 -14.21,130.94 ; J2.9@23.99,192.97 -6.84,132.24 ; J2.11@24.56,104.66 0,167 ; J2.9@24.56,195.34 0,133 ; J2.9@24.91,197.9 6.84,132.24 ; J2.9@24.99,200.62 14.21,130.94 ; pad.5@1005.99,1084 1005.99,988.38 967.61,950 740,950 685.4,895.4 685.4,895 554.62,895 357.31,697.69 357.31,385.31 122,150 50,150 ; J2.9@-23.14,190.53 0,167 ; J2.9@-23.14,190.53 0,167 ; J2.9@-23.14,190.53 0,167 ; J2.9@-23.14,190.53 0,167 ; -14.21,130.94 J2.9@0,200 ; J2.9@-12.75,197.44 0,167 ; J2.9@-12.75,197.44 0,167 ; J2.9@-12.75,197.44 0,167 ; J2.9@-12.75,197.47 6.84,132.24 ; J2.9@-12.75,197.44 0,167 ; -6.84,132.24 J2.9@12.75,197.47 ; -6.84,132.24 J2.9@0,200 ; 0,167 J2.9@23.14,190.53 ; 0,167 J2.9@12.75,197.44 ; 0,167 J2.9@0,200 ; 0,167 J2.9@23.14,190.53 ; 0,167 J2.9@12.75,197.44 ; 0,167 J2.9@0,200 ; 0,167 J2.9@23.14,190.53 ; 0,167 J2.9@12.75,197.44 ; 0,167 J2.9@0,200 ; 0,167 J2.9@23.14,190.53 ; 0,167 J2.9@12.75,197.44 ; 0,167 J2.9@0,200 ; J2.9@0,200 J2.11@0,100 50,150 ; J2.9@0,200 14.21,130.94 ; J2.9@0,200 6.84,132.24
TDI: J2.3 pad.8@1037.49,1217.86 | length 2431.4
  Primary Side w12: J2.3@-20.87,486.23 -44,544 ; J2.3@-10.1,491.82 -44,544 ; J2.3@8.18,510.1 -44,544 ; J2.3@13.77,520.87 -44,544 ; v1@668.45,1111.13 643.82,1120 ; v1@668.45,1128.87 643.82,1120 ; v1(670,1120) 643.82,1120 ; pad.8@1037.49,1217.86 1035,1220.35 1035,1303 985,1353 700,1353 ; -44,544 J2.3@0,500 -44,544 ; -44,544 -44,636.38 -24.38,656 179.82,656 643.82,1120 ; v1(685,1340) 687,1340 700,1353 ; v1(685,1340) 700,1353 ; v1(685,1340) 700,1353 ; 700,1353 680.8,1347.96 700,1353 ; 700,1353 692.28,1334.71 700,1353
  Secondary Side w12: v1(670,1120) 670,1329 v1(685,1340) 670,1278.46 ; v1@676.13,1341.5 670,1278.46 ; v1@693.57,1337.25 670,1278.46
TDO: J2.7 pad.6@1005.99,1217.86 | length 2790.3
  Primary Side w12: J2.7@-20.23,285.31 -56.46,356.46 ; J2.7@-9.91,291.59 -56.46,356.46 ; J2.7@8.41,309.91 -56.46,356.46 ; J2.7@14.69,320.23 -56.46,356.46 ; v1@633.54,1156.27 596.82,1112.01 ; v1(640,1305) 701,1305 730,1334 970.3,1334 1004.3,1300 1004.3,1219.55 pad.6@1005.99,1217.86 ; v1@640.79,1296.04 691,1305 v1@640.79,1313.96 ; v1@645.4,1142.8 596.82,1112.01 ; -56.46,356.46 J2.7@0,300 -63,363 -63,644.25 1.37,708.63 193.44,708.63 636.91,1152.09 v1(640,1150) 596.82,1112.01
  Secondary Side w12: v1@631.04,1150.79 640,1201 v1@648.96,1150.79 ; v1@631.04,1304.21 640,1254 v1@648.96,1304.21 ; v1(640,1150) v1(640,1305)
TMS: J2.1 pad.3@974.5,1084 | length 1508.5
  Primary Side w12: J2.1@-13.77,579.13 44,556 ; J2.1@-8.18,589.9 44,556 ; J2.1@0,600 44,556 ; J2.1@10.1,608.18 44,556 ; J2.1@20.87,613.77 44,556 ; pad.3@974.5,1084 975,1083.5 975,1003.06 950.97,979.03 576.81,979.03 153.78,556 44,556
pads on no net: "J30 - AMC1304.a2" "J30 - AMC1304.a5" "J30 - AMC1304.b1" "J30 - AMC1304.b2" "J30 - AMC1304.b3" "J30 - AMC1304.b4" "J30 - AMC1304.b5" "J30 - AMC1304.b6" "J30 - AMC1304.b7" "J30 - AMC1304.b8" "J30 - AMC1304.b9" "J30 - AMC1304.b10" "J30 - AMC1304.m0" "J30 - AMC1304.m1" J2.6 J17.2 J17.3 J17.4 J17.10 J17.11

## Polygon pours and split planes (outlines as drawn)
GND on Secondary Side "Secondary Side-GND" (solid, remove dead copper, pour order 2): -260,2520 6630,2520 6630,-220 -260,-220

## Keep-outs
Keep-Out Layer:
  the board outline again, w10

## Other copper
Primary Side:
  region net GND: 242,906 242,1158 156,1158 156,906 242,906
  region net +5V: 3647.5,1203.75 3572.5,1203.75 3632.5,1146.25
  text "1" at 6316.07,-4787.49 h75
  text "Primary Side" at 7746.14,-4801.77 h75
Secondary Side:
  text "2" at 6300.01,-4787.49 h75
  text "Secondary Side" at 7702.41,-4801.77 h75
